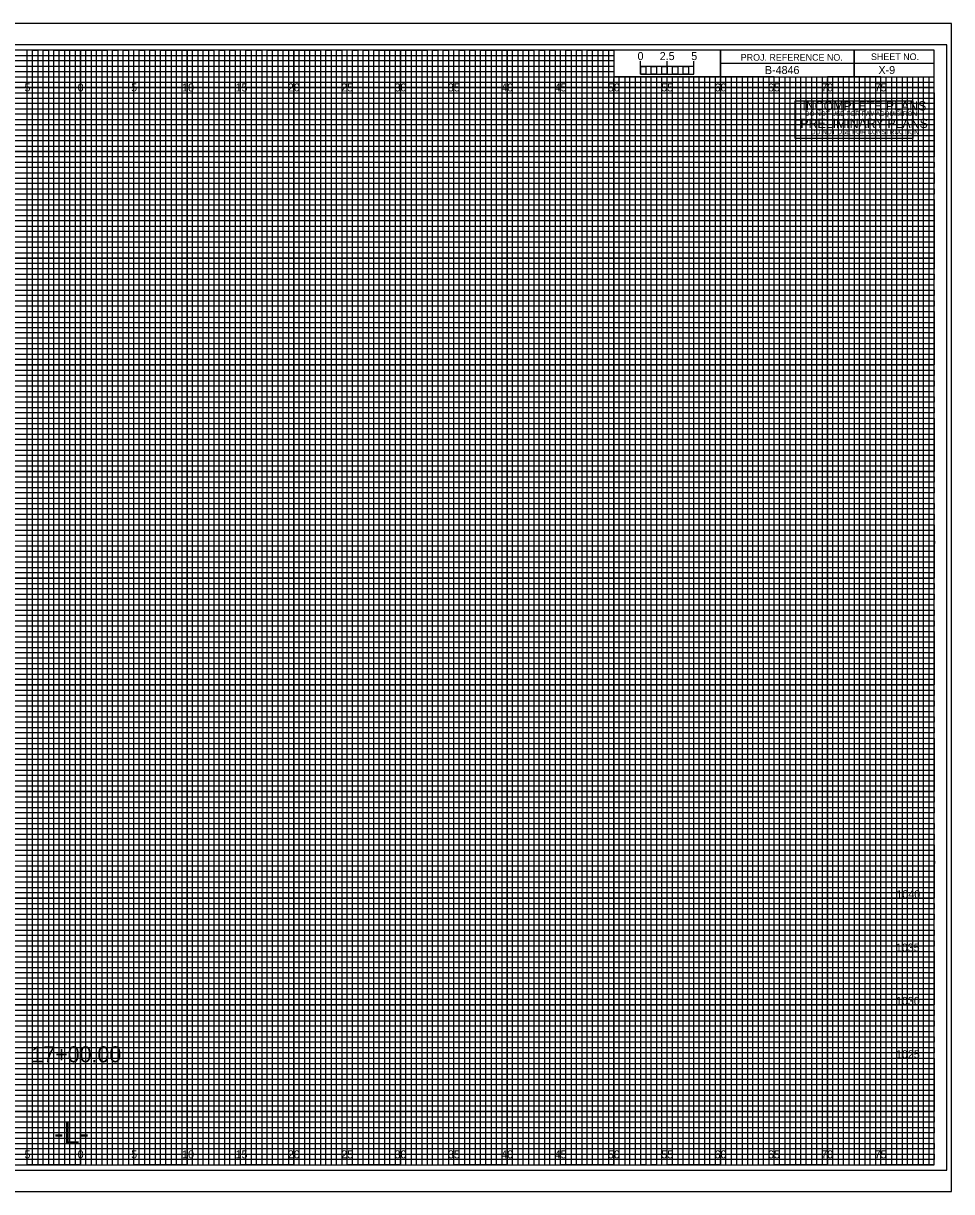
# Model space of a CAD drawing. Extents: x -7 to 162, y -2 to 987.
# Drawn here: x 74.6 to 161.7, y 877.5 to 987 of the extents above; entities that cross this region are included whole.
import ezdxf

# ---------------------------------------------------------------- set-up
doc = ezdxf.new("R2010")
doc.units = 0
for name, color, linetype in [('Default', 7, 'Continuous'), ('Exist Cross Section Cell', 7, 'Continuous'), ('Exist XS Center Line Elevation Label', 7, 'Continuous'), ('Exist XS Ground Line', 7, 'Continuous'), ('Prop CMT Concrete Structures', 7, 'Continuous'), ('Prop CMT DNC', 7, 'Continuous'), ('Prop CMT Guardrail Graphics', 7, 'Continuous'), ('Prop CMT Guardrail Widen Shoulder', 7, 'Continuous'), ('Prop CMT Pvmt Course 1', 7, 'Continuous'), ('Prop CMT Pvmt Surface', 7, 'Continuous'), ('Prop CMT Pvmt Surface Shoulder', 7, 'Continuous'), ('Prop CMT Shld Paved Course 1', 7, 'Continuous'), ('Prop CMT Shoulder Point', 7, 'Continuous'), ('Prop CMT Slope Grass', 7, 'Continuous'), ('Prop CMT Subgrade Earthwork', 7, 'Continuous'), ('Prop XS SE Text', 7, 'Continuous'), ('Prop XS Side Slope Text', 7, 'Continuous'), ('Typical Text Label CELL', 7, 'Continuous')]:
    doc.layers.add(name, color=color, linetype=linetype)

msp = doc.modelspace()

# ---------------------------------------------------------------- linework, layer by layer
at = {"layer": 'Default'}
for points in [[(146.99, 977.97), (146.99, 979.73), (158.01, 979.73), (158.01, 977.97)], [(146.99, 976.2), (146.99, 977.97), (158.01, 977.97), (158.01, 976.2)]]:
    msp.add_lwpolyline(points, close=True, dxfattribs=at)
at = {"layer": 'Exist XS Center Line Elevation Label'}
for points in [[(72.5, 880), (77.5, 880), (77.5, 984.5), (82.5, 984.5), (82.5, 880), (87.5, 880), (87.5, 984.5), (92.5, 984.5), (92.5, 880), (97.5, 880), (97.5, 984.5), (102.5, 984.5), (102.5, 880), (107.5, 880), (107.5, 984.5), (112.5, 984.5), (112.5, 880), (117.5, 880), (117.5, 984.5), (122.5, 984.5), (122.5, 880), (127.5, 880), (127.5, 984.5), (129.97, 984.5), (130, 984.5), (130, 982), (132.5, 982), (132.5, 880), (137.5, 880), (137.5, 982), (142.5, 982), (142.5, 880), (147.5, 880), (147.5, 982), (152.5, 982), (152.5, 880), (157.5, 880), (157.5, 982)], [(0, 982), (137.5, 982)], [(0, 972.5), (160, 972.5), (160, 977.5), (0, 977.5)], [(0, 962.5), (160, 962.5), (160, 967.5), (0, 967.5)], [(0, 952.5), (160, 952.5), (160, 957.5), (0, 957.5)], [(0, 942.5), (160, 942.5), (160, 947.5), (0, 947.5)], [(0, 932.5), (160, 932.5), (160, 937.5), (0, 937.5)], [(0, 922.5), (160, 922.5), (160, 927.5), (0, 927.5)], [(0, 912.5), (160, 912.5), (160, 917.5), (0, 917.5)], [(0, 902.5), (160, 902.5), (160, 907.5), (0, 907.5)], [(0, 892.5), (160, 892.5), (160, 897.5), (0, 897.5)], [(0, 882.5), (160, 882.5), (160, 887.5), (0, 887.5)]]:
    msp.add_lwpolyline(points, dxfattribs=at)
at = {"layer": 'Exist XS Ground Line'}
for p, q in [((75, 984.5), (70, 984.5)), ((75, 880), (75, 984.5)), ((85, 984.5), (80, 984.5)), ((80, 984.5), (80, 880)), ((85, 880), (85, 984.5)), ((95, 984.5), (90, 984.5)), ((90, 984.5), (90, 880)), ((95, 880), (95, 984.5)), ((105, 984.5), (100, 984.5)), ((100, 984.5), (100, 880)), ((105, 880), (105, 984.5)), ((115, 984.5), (110, 984.5)), ((110, 984.5), (110, 880)), ((115, 880), (115, 984.5)), ((125, 984.5), (120, 984.5)), ((120, 984.5), (120, 880)), ((125, 880), (125, 984.5)), ((130, 984.5), (130, 880)), ((135, 880), (135, 982)), ((145, 982), (140, 982)), ((140, 982), (140, 880)), ((145, 880), (145, 982)), ((155, 982), (150, 982)), ((150, 982), (150, 880)), ((155, 880), (155, 982)), ((80, 880), (75, 880)), ((90, 880), (85, 880)), ((100, 880), (95, 880)), ((110, 880), (105, 880)), ((120, 880), (115, 880)), ((130, 880), (125, 880)), ((140, 880), (135, 880)), ((150, 880), (145, 880)), ((160, 880), (155, 880)), ((160, 880), (160, 880))]:
    msp.add_line(p, q, dxfattribs=at)
for points in [[(0, 980), (160, 980), (160, 975), (0, 975)], [(0, 970), (160, 970), (160, 965), (0, 965)], [(0, 960), (160, 960), (160, 955), (0, 955)], [(0, 950), (160, 950), (160, 945), (0, 945)], [(0, 940), (160, 940), (160, 935), (0, 935)], [(0, 930), (160, 930), (160, 925), (0, 925)], [(0, 920), (160, 920), (160, 915), (0, 915)], [(0, 910), (160, 910), (160, 905), (0, 905)], [(0, 900), (160, 900), (160, 895), (0, 895)], [(0, 890), (160, 890), (160, 885), (0, 885)]]:
    msp.add_lwpolyline(points, dxfattribs=at)
at = {"layer": 'Prop CMT Concrete Structures'}
for p, q in [((75, 880), (75, 984.5)), ((80, 880), (80, 984.5)), ((85, 880), (85, 984.5)), ((90, 880), (90, 984.5)), ((95, 880), (95, 984.5)), ((100, 880), (100, 984.5)), ((105, 880), (105, 984.5)), ((110, 880), (110, 984.5)), ((115, 880), (115, 984.5)), ((120, 880), (120, 984.5)), ((125, 880), (125, 984.5)), ((130, 880), (130, 981.84)), ((135, 880), (135, 981.84)), ((140, 880), (140, 981.84)), ((145, 880), (145, 981.84)), ((150, 880), (150, 981.84)), ((155, 880), (155, 981.84)), ((0, 980), (160, 980)), ((0, 975), (160, 975)), ((0, 970), (160, 970)), ((0, 965), (160, 965)), ((0, 960), (160, 960)), ((0, 955), (160, 955)), ((0, 950), (160, 950)), ((0, 945), (160, 945)), ((0, 940), (160, 940)), ((0, 935), (160, 935)), ((0, 930), (160, 930)), ((0, 925), (160, 925)), ((0, 920), (160, 920)), ((0, 915), (160, 915)), ((0, 910), (160, 910)), ((0, 905), (160, 905)), ((0, 900), (160, 900)), ((0, 895), (160, 895)), ((0, 890), (160, 890)), ((0, 885), (160, 885))]:
    msp.add_line(p, q, dxfattribs=at)
at = {"layer": 'Prop CMT Guardrail Widen Shoulder'}
for p, q in [((161.65, 987), (-6.7, 987)), ((-6.7, 877.5), (161.65, 877.5))]:
    msp.add_line(p, q, dxfattribs=at)
at = {"layer": 'Prop CMT Pvmt Course 1'}
msp.add_lwpolyline([(-6.7, 877.5), (161.65, 877.5), (161.65, 987), (-6.7, 987)], close=True, dxfattribs=at)
at = {"layer": 'Prop CMT Pvmt Surface'}
for p, q in [((133.5, 982), (133, 982)), ((133, 982), (133, 880)), ((133.5, 880), (133.5, 982)), ((134.5, 982), (134, 982)), ((134, 982), (134, 880)), ((134.5, 880), (134.5, 982)), ((133, 880), (132.5, 880)), ((134, 880), (133.5, 880))]:
    msp.add_line(p, q, dxfattribs=at)
for points in [[(75, 880), (75.5, 880), (75.5, 984.5), (76, 984.5), (76, 880)], [(76, 880), (76.5, 880), (76.5, 984.5), (77, 984.5), (77, 880)], [(77.5, 880), (78, 880), (78, 984.5), (78.5, 984.5), (78.5, 880)], [(78.5, 880), (79, 880), (79, 984.5), (79.5, 984.5), (79.5, 880)], [(80, 880), (80.5, 880), (80.5, 984.5), (81, 984.5), (81, 880)], [(81, 880), (81.5, 880), (81.5, 984.5), (82, 984.5), (82, 880)], [(82.5, 880), (83, 880), (83, 984.5), (83.5, 984.5), (83.5, 880)], [(83.5, 880), (84, 880), (84, 984.5), (84.5, 984.5), (84.5, 880)], [(85, 880), (85.5, 880), (85.5, 984.5), (86, 984.5), (86, 880)], [(86, 880), (86.5, 880), (86.5, 984.5), (87, 984.5), (87, 880)], [(87.5, 880), (88, 880), (88, 984.5), (88.5, 984.5), (88.5, 880)], [(88.5, 880), (89, 880), (89, 984.5), (89.5, 984.5), (89.5, 880)], [(90, 880), (90.5, 880), (90.5, 984.5), (91, 984.5), (91, 880)], [(91, 880), (91.5, 880), (91.5, 984.5), (92, 984.5), (92, 880)], [(92.5, 880), (93, 880), (93, 984.5), (93.5, 984.5), (93.5, 880)], [(93.5, 880), (94, 880), (94, 984.5), (94.5, 984.5), (94.5, 880)], [(95, 880), (95.5, 880), (95.5, 984.5), (96, 984.5), (96, 880)], [(96, 880), (96.5, 880), (96.5, 984.5), (97, 984.5), (97, 880)], [(97.5, 880), (98, 880), (98, 984.5), (98.5, 984.5), (98.5, 880)], [(98.5, 880), (99, 880), (99, 984.5), (99.5, 984.5), (99.5, 880)], [(100, 880), (100.5, 880), (100.5, 984.5), (101, 984.5), (101, 880)], [(101, 880), (101.5, 880), (101.5, 984.5), (102, 984.5), (102, 880)], [(102.5, 880), (103, 880), (103, 984.5), (103.5, 984.5), (103.5, 880)], [(103.5, 880), (104, 880), (104, 984.5), (104.5, 984.5), (104.5, 880)], [(105, 880), (105.5, 880), (105.5, 984.5), (106, 984.5), (106, 880)], [(106, 880), (106.5, 880), (106.5, 984.5), (107, 984.5), (107, 880)], [(107.5, 880), (108, 880), (108, 984.5), (108.5, 984.5), (108.5, 880)], [(108.5, 880), (109, 880), (109, 984.5), (109.5, 984.5), (109.5, 880)], [(110, 880), (110.5, 880), (110.5, 984.5), (111, 984.5), (111, 880)], [(111, 880), (111.5, 880), (111.5, 984.5), (112, 984.5), (112, 880)], [(112.5, 880), (113, 880), (113, 984.5), (113.5, 984.5), (113.5, 880)], [(113.5, 880), (114, 880), (114, 984.5), (114.5, 984.5), (114.5, 880)], [(115, 880), (115.5, 880), (115.5, 984.5), (116, 984.5), (116, 880)], [(116, 880), (116.5, 880), (116.5, 984.5), (117, 984.5), (117, 880)], [(117.5, 880), (118, 880), (118, 984.5), (118.5, 984.5), (118.5, 880)], [(118.5, 880), (119, 880), (119, 984.5), (119.5, 984.5), (119.5, 880)], [(120, 880), (120.5, 880), (120.5, 984.5), (121, 984.5), (121, 880)], [(121, 880), (121.5, 880), (121.5, 984.5), (122, 984.5), (122, 880)], [(122.5, 880), (123, 880), (123, 984.5), (123.5, 984.5), (123.5, 880)], [(123.5, 880), (124, 880), (124, 984.5), (124.5, 984.5), (124.5, 880)], [(125, 880), (125.5, 880), (125.5, 984.5), (126, 984.5), (126, 880)], [(126, 880), (126.5, 880), (126.5, 984.5), (127, 984.5), (127, 880)], [(127.5, 880), (128, 880), (128, 984.5), (128.5, 984.5), (128.5, 880)], [(128.5, 880), (129, 880), (129, 984.5), (129.5, 984.5), (129.5, 880)], [(130, 880), (130.5, 880), (130.5, 982), (131.01, 982), (131.01, 880)], [(131, 880), (131.5, 880), (131.5, 982), (132, 982), (132, 880)], [(135, 880), (135.49, 880), (135.49, 982), (136, 982), (136, 880)], [(136, 880), (136.5, 880), (136.5, 982), (137.03, 982), (137.03, 880)], [(137.5, 880), (138, 880), (138, 982), (138.5, 982), (138.5, 880)], [(138.5, 880), (139, 880), (139, 982), (139.5, 982), (139.5, 880)], [(140, 880), (140.5, 880), (140.5, 982), (141, 982), (141, 880)], [(141, 880), (141.5, 880), (141.5, 982), (142, 982), (142, 880)], [(142.5, 880), (143, 880), (143, 982), (143.5, 982), (143.5, 880)], [(143.5, 880), (144, 880), (144, 982), (144.5, 982), (144.5, 880)], [(145, 880), (145.5, 880), (145.5, 982), (146, 982), (146, 880)], [(146, 880), (146.5, 880), (146.5, 982), (147, 982), (147, 880)], [(147.5, 880), (148, 880), (148, 982), (148.5, 982), (148.5, 880)], [(148.5, 880), (149, 880), (149, 982), (149.5, 982), (149.5, 880)], [(150, 880), (150.5, 880), (150.5, 982), (151, 982), (151, 880)], [(151, 880), (151.5, 880), (151.5, 982), (152, 982), (152, 880)], [(152.5, 880), (153, 880), (153, 982), (153.5, 982), (153.5, 880)], [(153.5, 880), (154, 880), (154, 982), (154.5, 982), (154.5, 880)], [(155, 880), (155.5, 880), (155.5, 982), (156, 982), (156, 880)], [(156, 880), (156.5, 880), (156.5, 982), (157, 982), (157, 880)], [(157.5, 880), (158, 880), (158, 982), (158.5, 982), (158.5, 880)], [(158.5, 880), (159, 880), (159, 982), (159.5, 982), (159.5, 880)]]:
    msp.add_lwpolyline(points, dxfattribs=at)
at = {"layer": 'Prop CMT Pvmt Surface Shoulder'}
for p, q in [((132.5, 982.25), (132.5, 983.45)), ((132.5, 982.95), (132.5, 983.45)), ((135, 982.25), (135, 983.45)), ((137.5, 982.25), (137.5, 983.45)), ((137.5, 982.95), (137.5, 983.45))]:
    msp.add_line(p, q, dxfattribs=at)
for points in [[(137.5, 982.95), (132.5, 982.95), (132.5, 982.25), (137.5, 982.25)], [(132.5, 982.95), (133, 982.95), (133, 982.25), (132.5, 982.25)], [(133.5, 982.95), (134, 982.95), (134, 982.25), (133.5, 982.25)], [(134.5, 982.95), (135, 982.95), (135, 982.25), (134.5, 982.25)], [(135.5, 982.95), (136, 982.95), (136, 982.25), (135.5, 982.25)], [(136.5, 982.95), (137, 982.95), (137, 982.25), (136.5, 982.25)]]:
    msp.add_lwpolyline(points, close=True, dxfattribs=at)
at = {"layer": 'Prop CMT Shld Paved Course 1'}
for p, q in [((0, 984), (130, 984)), ((130, 983.49), (0, 983.49)), ((130, 984), (130, 983.49)), ((0, 983), (130, 983)), ((130, 982.45), (0, 982.45)), ((130, 983), (130, 982.45)), ((0, 981.5), (160, 981.5))]:
    msp.add_line(p, q, dxfattribs=at)
for points in [[(0, 981), (135, 981), (160, 981), (160, 981), (0, 981)], [(0, 980.5), (160, 980.5), (160, 979.5), (0, 979.5)], [(0, 979), (160, 979), (160, 978.5), (0, 978.49)], [(0, 978), (160, 978), (160, 977), (0, 977)], [(0, 976.5), (160, 976.5), (160, 976), (0, 976)], [(0, 975.5), (160, 975.5), (160, 974.5), (0, 974.5)], [(0, 974), (160, 974), (160, 973.5), (0, 973.5)], [(0, 973), (160, 973), (160, 972), (0, 972)], [(0, 971.5), (160, 971.5), (160, 971), (0, 971)], [(0, 970.5), (160, 970.5), (160, 969.5), (0, 969.5)], [(0, 969), (160, 969), (160, 968.5), (0, 968.5)], [(0, 968), (160, 968), (160, 966.98), (160, 966.5), (160, 966), (0, 966)], [(0, 967), (160, 967), (160, 966.5), (0, 966.5)], [(0, 965.5), (160, 965.5), (160, 964.5), (0, 964.51)], [(0, 964.51), (160, 964.5), (160, 964), (0, 964)], [(0, 963.5), (160, 963.5), (160, 963), (0, 963)], [(0, 962), (160, 962), (160, 961.5), (0, 961.5)], [(0, 961), (160, 961), (160, 960.5), (0, 960.5)], [(-0.04, 959.45), (160, 959.45), (160, 958.94), (-0.04, 958.94)], [(0, 958.5), (160, 958.5), (160, 958), (0, 958)], [(0, 957), (160, 957), (160, 956.5), (0, 956.5)], [(0, 956), (160, 956), (160, 955.5), (0, 955.5)], [(0, 954.5), (160, 954.5), (160, 954), (0, 954)], [(0, 953.5), (160, 953.5), (160, 953), (0, 953)], [(0, 952), (160, 952), (160, 951.5), (0, 951.5)], [(0, 951), (160, 951), (160, 950.5), (0, 950.5)], [(0, 949.5), (160, 949.5), (160, 948.99), (0, 949)], [(0, 948.5), (160, 948.5), (160, 948), (0, 948)], [(0, 947), (160, 947), (160, 946.5), (0, 946.5)], [(0, 946), (160, 946), (160, 945.5), (0, 945.5)], [(0, 944.5), (160, 944.5), (160, 944), (0, 944)], [(0, 943.5), (160, 943.5), (160, 943), (0, 943)], [(0, 942), (160, 942), (160, 941.5), (0, 941.5)], [(0, 941), (160, 941), (160, 940.5), (0, 940.5)], [(0, 939.5), (160, 939.5), (160, 939), (0, 939)], [(0, 938.5), (160.03, 938.46), (160, 938), (0, 938)], [(0, 937), (160, 937), (160, 936.5), (0, 936.5)], [(0, 936), (160, 936), (160, 935.5), (0, 935.5)], [(0, 934.5), (160, 934.5), (160, 934), (0, 934)], [(0, 933.5), (160, 933.5), (160, 933), (0, 933)], [(0, 932), (160, 932), (160, 931.5), (0, 931.5)], [(0, 931), (160, 931), (160, 930.5), (0, 930.5)], [(0, 929.5), (160, 929.5), (160, 929), (0, 929)], [(0, 928.5), (160, 928.5), (160, 928), (0, 928)], [(0, 927), (160, 927), (160, 926.5), (0, 926.5)], [(0, 926), (160, 926), (160, 925.5), (0, 925.5)], [(0, 924.5), (160, 924.5), (160, 924), (0, 924)], [(0, 923.5), (160, 923.5), (160, 923), (0, 923)], [(0, 922), (160, 922), (160, 921.5), (0, 921.5)], [(0, 921), (160, 921), (160, 920.5), (0, 920.5)], [(0, 919.5), (160, 919.5), (160, 918.99), (0, 919)], [(0, 918.5), (160, 918.5), (160, 918), (0, 918)], [(0, 917), (160, 917), (160, 916.5), (0, 916.5)], [(0, 916), (160, 916), (160, 915.5), (0, 915.5)], [(0, 914.5), (160, 914.5), (160, 914), (0, 914)], [(0, 913.5), (160, 913.5), (160, 913), (0, 913)], [(0, 912), (160, 912), (160, 911.5), (0, 911.5)], [(0, 911), (160, 911), (160, 910.5), (0, 910.5)], [(0, 909.5), (160, 909.5), (160, 909), (0, 909)], [(0, 908.5), (160.03, 908.46), (160, 908), (0, 908)], [(0, 907), (160, 907), (160, 906.5), (0, 906.5)], [(0, 906), (160, 906), (160, 905.5), (0, 905.5)], [(0, 904.5), (160, 904.5), (160, 904), (0, 904)], [(0, 903.5), (160, 903.5), (160, 903), (0, 903)], [(0, 902), (160, 902), (160, 901.5), (0, 901.5)], [(0, 901), (160, 901), (160, 900.5), (0, 900.5)], [(0, 899.5), (160, 899.5), (160, 899), (0, 899)], [(0, 898.5), (160, 898.5), (160, 898), (0, 898)], [(0, 897), (160, 897), (160, 896.5), (0, 896.5)], [(0, 896), (160, 896), (160, 895.5), (0, 895.5)], [(0, 894.5), (160, 894.5), (160, 894), (0, 894)], [(0, 893.5), (160, 893.5), (160, 893), (0, 893)], [(0, 892), (160, 892), (160, 891.5), (0, 891.5)], [(0, 891), (160, 891), (160, 890.5), (0, 890.5)], [(0, 889.5), (160, 889.5), (160, 889), (0, 889)], [(0, 888.5), (160, 888.5), (160, 888), (0, 888)], [(0, 887), (160, 887), (160, 886.5), (0, 886.5)], [(0, 886), (160, 886), (160, 885.5), (0, 885.5)], [(0, 884.5), (160, 884.5), (160, 884), (0, 884)], [(0, 883.5), (160, 883.5), (160, 883), (0, 883)], [(0, 882), (160, 882), (160, 881.5), (0, 881.5)], [(0, 881), (160, 881), (160, 880.5), (0, 880.5)]]:
    msp.add_lwpolyline(points, dxfattribs=at)
at = {"layer": 'Prop CMT Slope Grass'}
msp.add_lwpolyline([(-5.4, 879.5), (161.2, 879.5), (161.2, 985), (-5.4, 985)], close=True, dxfattribs=at)
at = {"layer": 'Prop CMT Subgrade Earthwork'}
for p, q in [((152.5, 984.5), (152.5, 982)), ((152.5, 982), (152.5, 984.5)), ((160, 983.25), (140, 983.25)), ((140, 983.25), (140, 982)), ((140, 982), (160, 982))]:
    msp.add_line(p, q, dxfattribs=at)
for points in [[(160, 984.5), (0, 984.5), (0, 880), (160, 880)], [(140, 984.5), (130, 984.5), (130, 982.01), (140, 982.01)], [(160, 984.5), (140, 984.5), (140, 982), (160, 982)]]:
    msp.add_lwpolyline(points, close=True, dxfattribs=at)

# ---------------------------------------------------------------- texts
at = {"layer": 'Default'}
for s, height, p in [('INCOMPLETE PLANS', 0.864, (147.66, 978.84)), ('PRELIMINARY PLANS', 0.864, (147.47, 977.19)), ('DO NOT USE FOR R/W ACQUISITION', 0.432, (147.9, 978.32)), ('DO NOT USE FOR CONSTRUCTION', 0.432, (148.46, 976.61))]:
    msp.add_text(s, height=height, dxfattribs=at).set_placement(p)
at = {"layer": 'Exist Cross Section Cell'}
for s, p in [('5', (74.74, 980.62)), ('0', (79.73, 980.62)), ('0', (79.73, 980.62)), ('5', (84.74, 980.62)), ('10', (89.52, 980.62)), ('15', (94.53, 980.62)), ('20', (99.43, 980.62)), ('25', (104.44, 980.62)), ('30', (109.43, 980.62)), ('35', (114.44, 980.62)), ('40', (119.43, 980.62)), ('45', (124.44, 980.62)), ('50', (129.43, 980.62)), ('55', (134.44, 980.62)), ('60', (139.43, 980.62)), ('65', (144.44, 980.62)), ('70', (149.43, 980.62)), ('75', (154.44, 980.62)), ('5', (74.74, 880.62)), ('0', (79.73, 880.62)), ('0', (79.73, 880.62)), ('5', (84.74, 880.62)), ('10', (89.52, 880.62)), ('15', (94.53, 880.62)), ('20', (99.43, 880.62)), ('25', (104.44, 880.62)), ('30', (109.43, 880.62)), ('35', (114.44, 880.62)), ('40', (119.43, 880.62)), ('45', (124.44, 880.62)), ('50', (129.43, 880.62)), ('55', (134.44, 880.62)), ('60', (139.43, 880.62)), ('65', (144.44, 880.62)), ('70', (149.43, 880.62)), ('75', (154.44, 880.62))]:
    msp.add_text(s, height=0.75, dxfattribs=at).set_placement(p)
at = {"layer": 'Prop CMT DNC'}
msp.add_text('-L-', height=2, dxfattribs=at).set_placement((77.53, 882))
at = {"layer": 'Prop CMT Guardrail Graphics'}
msp.add_text('B-4846', height=0.75, dxfattribs=at).set_placement((144.15, 982.25))
at = {"layer": 'Prop CMT Pvmt Surface Shoulder'}
msp.add_text('0', height=0.75, dxfattribs=at).set_placement((132.21, 983.56))
at = {"layer": 'Prop CMT Shoulder Point'}
for s, p in [('2.5', (134.29, 983.56)), ('5', (137.24, 983.56))]:
    msp.add_text(s, height=0.75, dxfattribs=at).set_placement(p)
at = {"layer": 'Prop CMT Subgrade Earthwork'}
for s, p in [('PROJ. REFERENCE NO.', (141.88, 983.5)), ('SHEET NO.', (154.09, 983.56))]:
    msp.add_text(s, height=0.625, dxfattribs=at).set_placement(p)
at = {"layer": 'Prop XS SE Text'}
msp.add_text('X-9', height=0.75, dxfattribs=at).set_placement((154.79, 982.25))
at = {"layer": 'Prop XS Side Slope Text'}
msp.add_text('17+00.00', height=1.5, dxfattribs=at).set_placement((75.39, 889.62))
at = {"layer": 'Typical Text Label CELL'}
for s, p in [('1040', (156.47, 905)), ('1035', (156.42, 900)), ('1030', (156.43, 895)), ('1025', (156.43, 890))]:
    msp.add_text(s, height=0.75, dxfattribs=at).set_placement(p)

doc.saveas('drawing.dxf')
